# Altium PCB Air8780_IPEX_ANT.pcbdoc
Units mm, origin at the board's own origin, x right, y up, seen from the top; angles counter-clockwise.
Board outline 53.7 x 68.7 mm, 2 copper layers (Top Layer, Bottom Layer); 1 components, 0 nets, 44 pads, 0 vias.
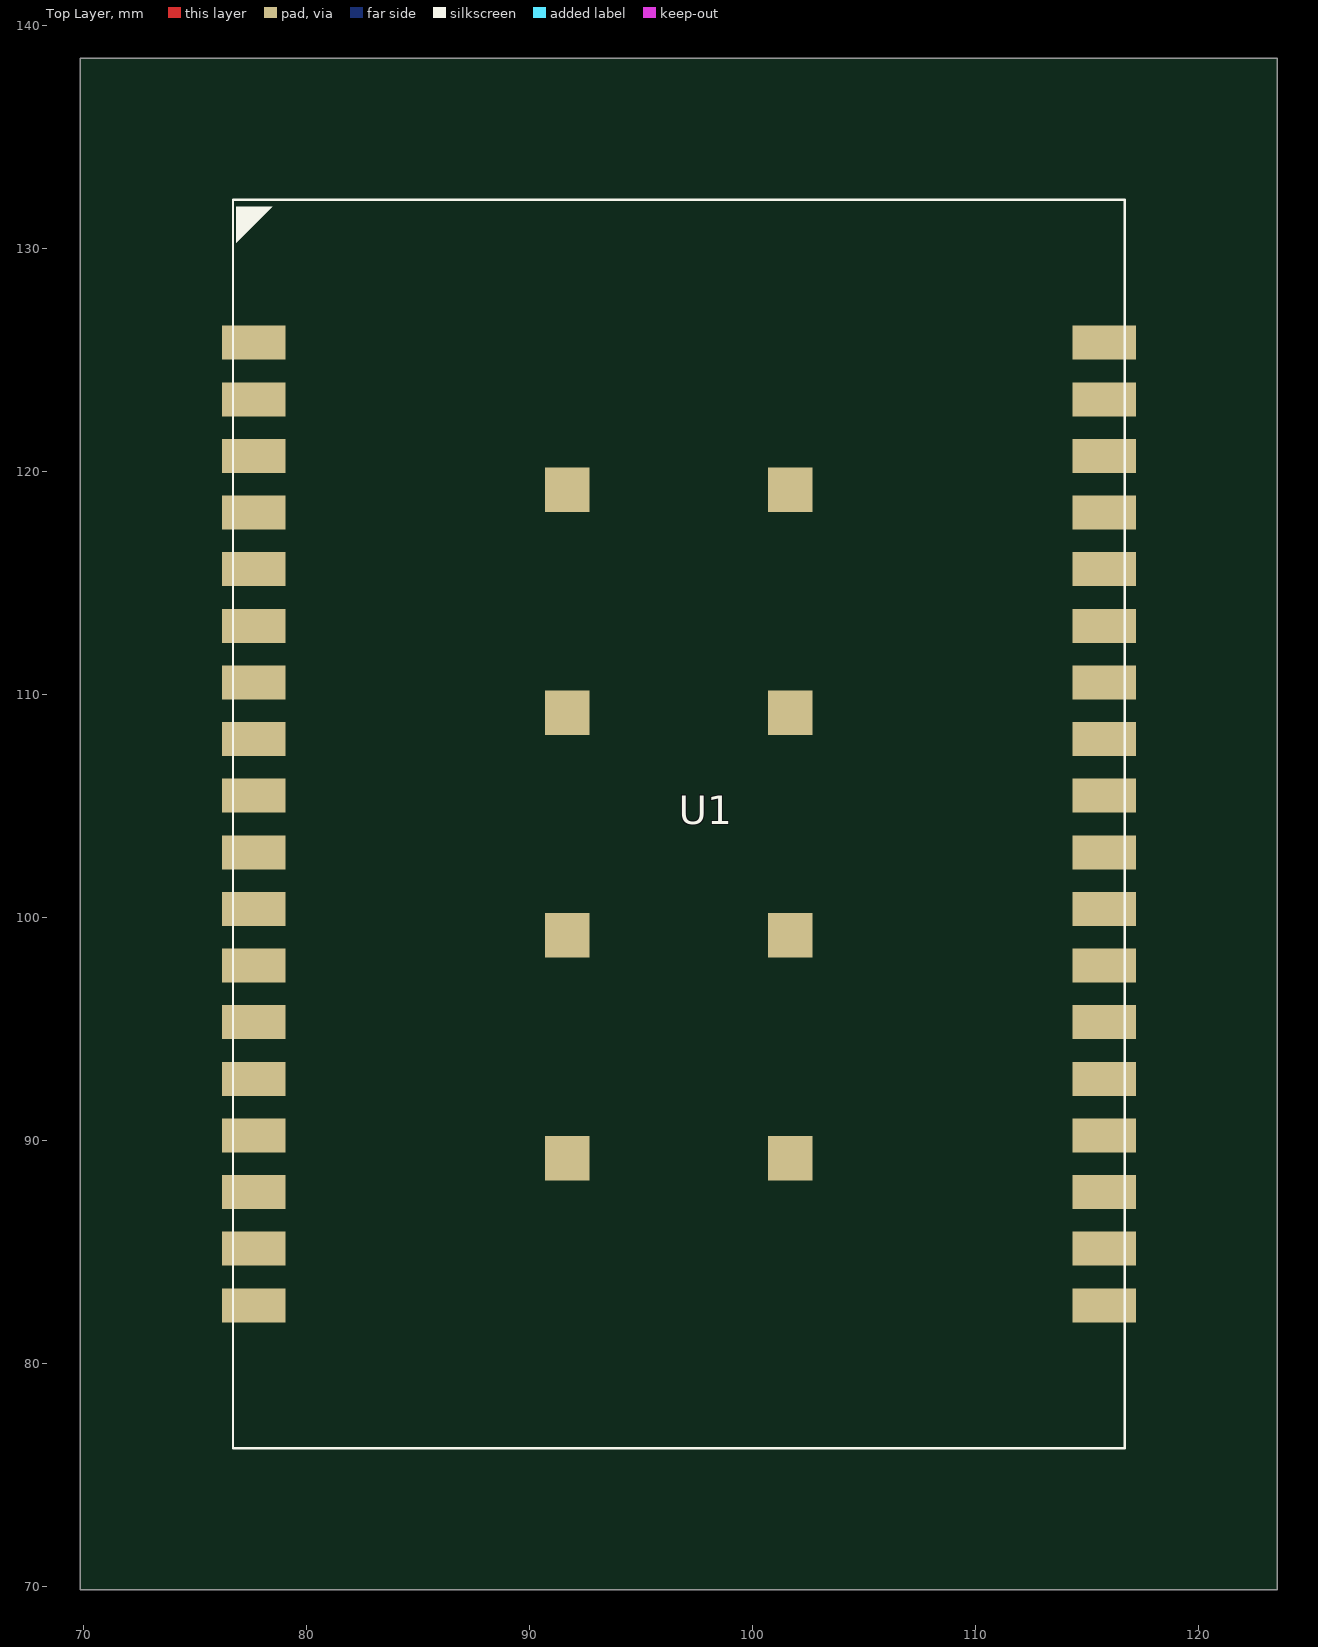
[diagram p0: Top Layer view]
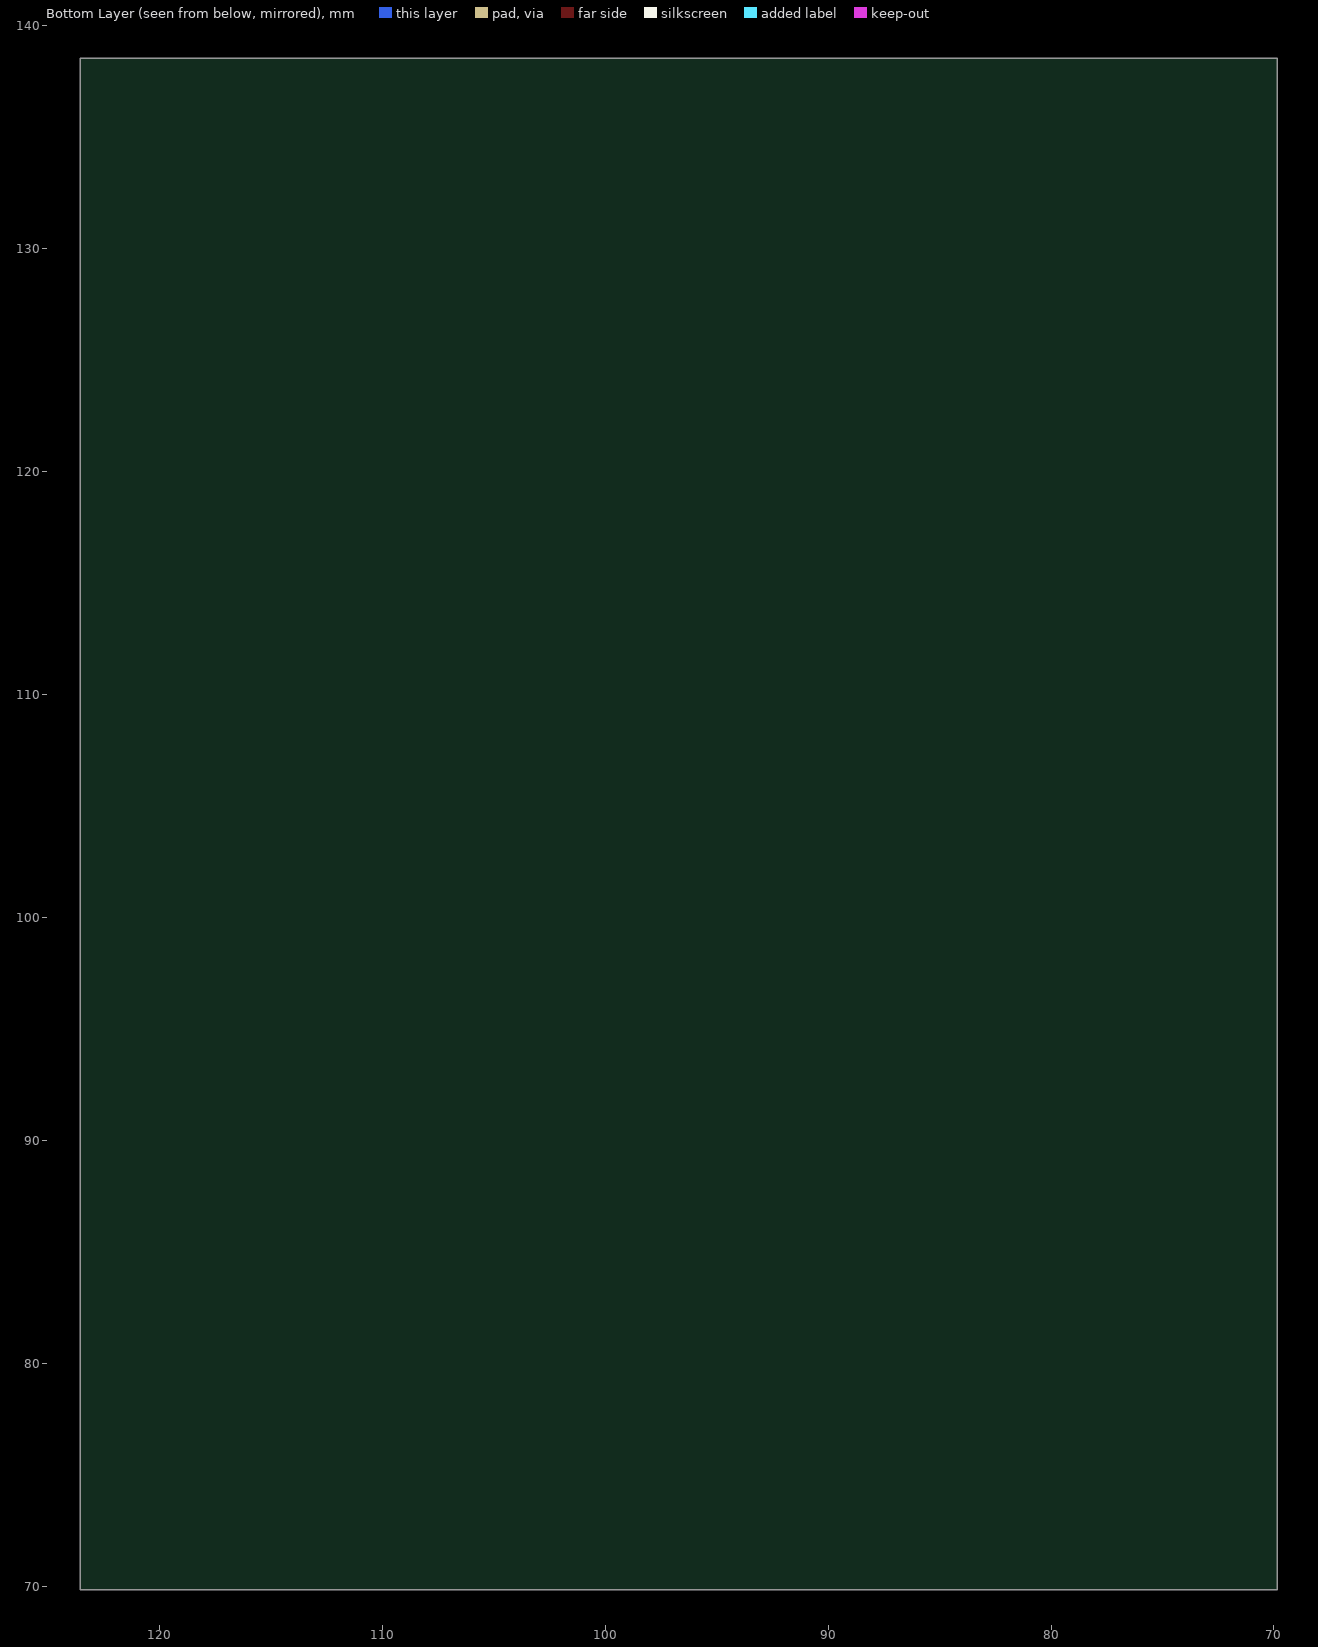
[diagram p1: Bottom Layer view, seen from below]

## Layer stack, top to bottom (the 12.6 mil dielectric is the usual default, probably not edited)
Top Layer: signal copper (thickness not stored)
Dielectric: dielectric 0.32, FR-4, Dk 4.8
Bottom Layer: signal copper (thickness not stored)

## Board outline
123.55,69.85 69.85,69.85 69.85,138.55 123.55,138.55

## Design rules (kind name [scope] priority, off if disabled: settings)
BoardOutlineClearance safeClearance [All] p0: genericclearance=0.254 ignorepadtopadclearanceinfootprint=FALSE except(0: Region-OutlineEdge Poly-OutlineEdge Text-OutlineEdge Sheet-OutlineEdge Hole-OutlineEdge Track-CutoutEdge SMDPad-CutoutEdge THPad-CutoutEdge Via-CutoutEdge Fill-CutoutEdge Region-CutoutEdge Poly-CutoutEdge Text-CutoutEdge Sheet-CutoutEdge Hole-CutoutEdge Arc-SplitContinuation Track-SplitContinuation SMDPad-SplitContinuation THPad-SplitContinuation Via-SplitContinuation Fill-SplitContinuation Poly-SplitContinuation Region-SplitContinuation Text-SplitContinuation; 0.152: Track-OutlineEdge SMDPad-OutlineEdge THPad-OutlineEdge Via-OutlineEdge Fill-OutlineEdge)
Clearance safeClearance [All] p1: gap=0.178 ignorepadtopadclearanceinfootprint=FALSE except(0: Region-Track Poly-Track Region-SMDPad Poly-SMDPad Region-THPad Poly-THPad Region-Via Poly-Via Region-Fill Poly-Fill Text-Fill Track-Region SMDPad-Region THPad-Region Via-Region Fill-Region Region-Region Poly-Region Text-Region Sheet-Region Hole-Region Track-Poly SMDPad-Poly THPad-Poly Via-Poly Fill-Poly Region-Poly Poly-Poly Text-Poly Sheet-Poly Hole-Poly Fill-Text Region-Text Poly-Text Text-Text Sheet-Text Hole-Text Region-Sheet Poly-Sheet Text-Sheet Sheet-Sheet Hole-Sheet Region-Hole Poly-Hole Text-Hole Sheet-Hole; 0.152: Track-Track SMDPad-Track THPad-Track Via-Track Fill-Track Text-Track Sheet-Track Hole-Track Track-SMDPad SMDPad-SMDPad THPad-SMDPad Via-SMDPad Fill-SMDPad Text-SMDPad Sheet-SMDPad Hole-SMDPad Track-THPad SMDPad-THPad THPad-THPad Via-THPad Fill-THPad Text-THPad Sheet-THPad Hole-THPad Track-Via SMDPad-Via THPad-Via Via-Via Fill-Via Text-Via Sheet-Via Hole-Via Track-Fill SMDPad-Fill THPad-Fill Via-Fill Fill-Fill Sheet-Fill Hole-Fill Track-Text SMDPad-Text THPad-Text Via-Text Track-Sheet SMDPad-Sheet THPad-Sheet Via-Sheet Fill-Sheet Track-Hole SMDPad-Hole THPad-Hole Via-Hole Fill-Hole Hole-Hole)
PasteMaskExpansion Common [All] p1: expansion=0
SolderMaskExpansion Common [All] p1: useseparateexpansions=TRUE expansion=0 expansionbottom=0
Width trackWidth [All] p1: maxlimit=12 minlimit=12 preferedwidth=12

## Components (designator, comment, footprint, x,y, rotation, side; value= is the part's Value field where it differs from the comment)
U1 "AIR8780_IPEX_ANT" AIR8780_IPEX_ANT 96.7,104.2 r0 top

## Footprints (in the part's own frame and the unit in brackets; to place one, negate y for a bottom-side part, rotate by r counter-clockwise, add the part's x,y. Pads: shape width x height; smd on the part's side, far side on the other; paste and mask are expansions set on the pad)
AIR8780_IPEX_ANT [mm]
  rect 2.85x1.524 smd: 1(-19.075,21.59) 2(-19.075,19.05) 3(-19.075,16.51) 4(-19.075,13.97) 5(-19.075,11.43) 6(-19.075,8.89) 7(-19.075,6.35) 8(-19.075,3.81) 9(-19.075,1.27) 10(-19.075,-1.27) 11(-19.075,-3.81) 12(-19.075,-6.35) 13(-19.075,-8.89) 14(-19.075,-11.43) 15(-19.075,-13.97) 16(-19.075,-16.51) 17(-19.075,-19.05) 18(-19.075,-21.59) 19(19.075,-21.59) 20(19.075,-19.05) 21(19.075,-16.51) 22(19.075,-13.97) 23(19.075,-11.43) 24(19.075,-8.89) 25(19.075,-6.35) 26(19.075,-3.81) 27(19.075,-1.27) 28(19.075,1.27) 29(19.075,3.81) 30(19.075,6.35) 31(19.075,8.89) 32(19.075,11.43) 33(19.075,13.97) 34(19.075,16.51) 35(19.075,19.05) 36(19.075,21.59)
  rect 2x2 smd: 37(-5,15) 38(-5,5) 39(-5,-5) 40(-5,-15) 41(5,-15) 42(5,-5) 43(5,5) 44(5,15)
  silkscreen extent -20,-28 20,28

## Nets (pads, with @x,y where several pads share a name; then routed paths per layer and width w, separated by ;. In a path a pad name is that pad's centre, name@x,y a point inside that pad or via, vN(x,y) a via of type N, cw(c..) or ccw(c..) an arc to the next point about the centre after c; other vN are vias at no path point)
pads on no net: U1.1 U1.2 U1.3 U1.4 U1.5 U1.6 U1.7 U1.8 U1.9 U1.10 U1.11 U1.12 U1.13 U1.14 U1.15 U1.16 U1.17 U1.18 U1.19 U1.20 U1.21 U1.22 U1.23 U1.24 U1.25 U1.26 U1.27 U1.28 U1.29 U1.30 U1.31 U1.32 U1.33 U1.34 U1.35 U1.36 U1.37 U1.38 U1.39 U1.40 U1.41 U1.42 U1.43 U1.44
